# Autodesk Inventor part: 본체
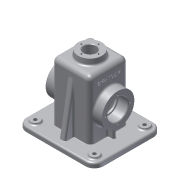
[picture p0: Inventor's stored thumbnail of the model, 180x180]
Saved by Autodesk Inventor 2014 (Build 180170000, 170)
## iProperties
Created: 2016-06
Part Number: 본체
Material: 알루미늄 6061
Document SubType Name: Modeling
Designer: user
Mass: 806.272 g
Surface Area: 909.625 cm^2
Volume: 297.517 cm^3
Density: 2.71 g/cm^3
Appearance: 알루미늄 - 평지
Author: user
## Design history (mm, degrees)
sketch "스케치1"
  geometry: L1 (-50, -52.5)-(50, -52.5); L2 (60, -42.5)-(60, 42.5); L3 (50, 52.5)-(-50, 52.5); L4 (-60, 42.5)-(-60, -42.5); L5 (-60, -52.5)-(60, 52.5); L6 (60, -52.5)-(-60, 52.5); A1 r 10 centre (-50, 42.5) between (-50, 52.5) and (-60, 42.5); A2 r 10 centre (50, 42.5) between (60, 42.5) and (50, 52.5); A3 r 10 centre (50, -42.5) between (50, -52.5) and (60, -42.5); A4 r 10 centre (-50, -42.5) between (-60, -42.5) and (-50, -52.5); 1 further point
  constraints: 12 end point, 8 point on circle, 8 point on line, 8 tangent, 4 centre point, 3 equal radius, 2 midpoint, 2 parallel, 1 horizontal, 1 perpendicular
  dimensions: "d0" = 120 distance of L6.end L5.end; "d1" = 105 distance of L5.end L6.start; "d2" = 10 radius of A1
extrude "돌출1" new body sketch "스케치1" distance "d3" = 2; taper "d4" = 0 deg
sketch "스케치2"
  geometry: L1 (-60, 42.5)-(-60, -42.5) reference; L2 (50, 52.5)-(-50, 52.5) reference; L3 (-60, 42.5)-(-60, -42.5) reference; L4 (-50, -52.5)-(50, -52.5) reference; L5 (60, -42.5)-(60, 42.5) reference; L6 (-50, 57.5)-(50, 57.5); L7 (65, 42.5)-(65, -42.5); L8 (50, -57.5)-(-50, -57.5); L9 (-65, -42.5)-(-65, 42.5); A1 r 10 centre (-50, 42.5) between (-50, 52.5) and (-60, 42.5) reference; A2 r 10 centre (-50, -42.5) between (-60, -42.5) and (-50, -52.5) reference; A3 r 10 centre (50, -42.5) between (50, -52.5) and (60, -42.5) reference; A4 r 10 centre (50, 42.5) between (60, 42.5) and (50, 52.5) reference; A5 r 15 centre (50, 42.5) between (65, 42.5) and (50, 57.5); A6 r 15 centre (50, -42.5) between (50, -57.5) and (65, -42.5); A7 r 15 centre (-50, -42.5) between (-65, -42.5) and (-50, -57.5); A8 r 15 centre (-50, 42.5) between (-50, 57.5) and (-65, 42.5); 1 further point
  constraints: 8 end point, 8 point on circle, 4 centre point, 7 other
  dimensions: "d5" = 5 distance between parallel lines of L1 L9
extrude "돌출2" join sketch "스케치2" distance "d6" = 8; taper "d7" = 0 deg
sketch "스케치3"
  geometry: C1 r 7.5 at (-50, -42.5); C2 r 7.5 at (-50, 42.5); C3 r 7.5 at (50, 42.5); C4 r 7.5 at (50, -42.5); A1 r 15 centre (-50, 42.5) between (-50, 57.5) and (-65, 42.5) reference; A2 r 15 centre (-50, -42.5) between (-65, -42.5) and (-50, -57.5) reference; A3 r 15 centre (50, -42.5) between (50, -57.5) and (65, -42.5) reference; A4 r 15 centre (50, 42.5) between (65, 42.5) and (50, 57.5) reference; 1 further point
  constraints: 4 centre point, 4 coincident
  dimensions: "d8" = 15 diameter of C1; "d9" = 15 diameter of C2; "d10" = 15 diameter of C3; "d11" = 15 diameter of C4
extrude "돌출3" join sketch "스케치3" distance "d12" = 3; taper "d13" = 0 deg
fillet "모깎기1" dims "d14" = 3
sketch "스케치4"
  geometry: C1 r 7.5 at (0, 0) reference; C2 r 7.5 at (100, 0) reference; C3 r 7.5 at (100, -85) reference; C4 r 7.5 at (0, -85) reference; 5 further points
  constraints: 4 coincident
hole "구멍1" sketch "스케치4" at (0, 0), (100, 0), (100, -85), (0, -85) diameter "d15" = 6; stored, may be unused: countersink angle "d19" = 90 deg, drill point angle "d21" = 118 deg; dims "d16" = 6, "d17" = 4, "d18" = 2, "d20" = 8
sketch "스케치5"
  geometry: L1 (-32.5, -32.5)-(32.5, -32.5); L2 (32.5, -32.5)-(32.5, 32.5); L3 (32.5, 32.5)-(-32.5, 32.5); L4 (-32.5, 32.5)-(-32.5, -32.5); L5 (-32.5, -32.5)-(32.5, 32.5); L6 (32.5, -32.5)-(-32.5, 32.5); 1 further point
  constraints: 12 end point, 2 midpoint, 2 parallel, 1 horizontal, 1 perpendicular
  dimensions: "d22" = 65 distance of L3.end L2.end; "d23" = 65 distance of L2.end L1.end
extrude "돌출4" join sketch "스케치5" distance "d24" = 100; taper "d25" = 0 deg
fillet "모깎기2" dims "d26" = 8
fillet "모깎기3" dims "d27" = 8
node "작업 평면1"
sketch "스케치7"
  geometry: C1 r 20 at (0, 0); 1 further point
  constraints: 1 centre point, 1 coincident
  dimensions: "d29" = 40 diameter of C1
extrude "돌출5" join sketch "스케치7" stored distance "d30" = 100; taper "d31" = 5 deg
fillet "모깎기4" dims "d32" = 3
sketch "스케치8"
  geometry: L1 (-27.5, 27.5)-(27.5, 27.5); L2 (27.5, 27.5)-(27.5, -27.5); L3 (27.5, -27.5)-(-27.5, -27.5); L4 (-27.5, -27.5)-(-27.5, 27.5); L5 (-27.5, 27.5)-(27.5, -27.5); L6 (27.5, 27.5)-(-27.5, -27.5); 1 further point
  constraints: 12 end point, 2 midpoint, 2 parallel, 1 horizontal, 1 perpendicular
  dimensions: "d33" = 55 distance of L2.end L3.end; "d34" = 55 distance of L1.end L2.end
extrude "돌출6" cut sketch "스케치8" distance "d35" = 105; taper "d36" = 0 deg
fillet "모깎기5" dims "d37" = 3
fillet "모깎기6" dims "d38" = 3
sketch "스케치9"
  geometry: C1 r 20 at (0, 0) reference; 1 further point
  constraints: 1 coincident
hole "구멍2" sketch "스케치9" at (0, 0) diameter "d39" = 21; stored, may be unused: countersink angle "d43" = 90 deg, drill point angle "d45" = 118 deg; dims "d40" = 6, "d41" = 4, "d42" = 2, "d44" = 8
chamfer "모따기1" distance "d46" = 1; stored, may be unused: second distance "d47" = 2, angle "d48" = 45 deg
sketch "스케치10"
  geometry: C1 r 20 at (0, 0) reference; C2 r 11.5 at (0, 0) reference; A1 r 14.5 centre (0, 0) between (0, 14.5) and (14.5, 0); 2 further points
  constraints: 4 point on circle, 2 horizontal alignment, 2 vertical alignment, 1 centre point, 1 coincident
  dimensions: "d49" = 29 diameter of A1
hole "구멍3" sketch "스케치10" at (0, 14.5), (0, -14.5), (-14.5, 0), (14.5, 0) diameter "d50" = 2.459; stored, may be unused: countersink angle "d54" = 90 deg, drill point angle "d56" = 118 deg; dims "d51" = 7, "d52" = 4, "d53" = 2, "d55" = 9
sketch "스케치11"
  geometry: C1 r 27.5 at (-45, 24.5); 1 further point
  constraints: 1 centre point, 1 horizontal alignment
  dimensions: "d57" = 55 diameter of C1; "d58" = 55 distance of C1.centre point (10, 24.5)
extrude "돌출7" join sketch "스케치11" distance "d59" = 15; taper "d60" = 0 deg
sketch "스케치12"
  geometry: C1 r 27.5 at (0, 0) reference; 2 further points
  constraints: 1 coincident
hole "구멍4" sketch "스케치12" at (0, 0) diameter "d61" = 30; stored, may be unused: countersink angle "d65" = 90 deg, drill point angle "d67" = 0 deg; dims "d62" = 7, "d63" = 35, "d64" = 17, "d66" = 20
chamfer "모따기2" distance "d68" = 1; stored, may be unused: second distance "d69" = 2, angle "d70" = 45 deg
sketch "스케치13"
  geometry: C1 r 27.5 at (0, 0) reference; C2 r 18.5 at (0, 0) reference; A1 r 21 centre (0, 0) between (0, 21) and (21, 0); 3 further points
  constraints: 4 point on circle, 2 horizontal alignment, 2 vertical alignment, 1 centre point, 1 coincident
  dimensions: "d71" = 42 diameter of A1
hole "구멍5" sketch "스케치13" at (0, 21), (0, -21), (-21, 0), (21, 0) diameter "d72" = 3.242; stored, may be unused: countersink angle "d76" = 90 deg, drill point angle "d78" = 118 deg; dims "d73" = 8, "d74" = 35, "d75" = 17, "d77" = 10
sketch "스케치14"
  geometry: L1 (47.5, 27.5)-(32.5, 27.5) reference; L2 (-50, 10)-(50, 10) reference; L3 (42.5, 27.5)-(42.5, 10); L4 (27.5, 0)-(27.5, 102) reference; 1 further point
  constraints: 2 end point, 2 point on line, 1 vertical
  dimensions: "d79" = 15 distance between parallel lines of L3 L4
feature "리브1" sketch "스케치14" dims "d80" = 1, "d81" = 6, "d82" = 0, "d83" = 0, "d84" = 1, "d85" = 1
fillet "모깎기7" dims "d86" = 3
fillet "모깎기8" dims "d87" = 3
sketch "스케치15"
  geometry: L1 (0, -8)-(92, -8) reference; L2 (-18, 4.5)-(-18, 44.5) reference; A1 r 30.5 centre (47, 24.5) between (28.834, 49) and (28.834, 0) reference; 2 further points
  constraints: 1 horizontal alignment, 1 other
  dimensions: "d88" = 32.5 distance from line of point (8, 24.5) L1 (derived); "d89" = 26 distance from line of point (8, 24.5) L2
feature "엠보싱1" sketch "스케치15" dims "d90" = 0.5, "d91" = 0
sketch "스케치16"
  geometry: L1 (-32.5, 10)-(-32.5, 102) reference; L2 (-32, 10)-(-53, 10) reference; L3 (-57.5, 2)-(-57.5, 7) reference; L4 (-47.5, 10)-(-32.5, 95.069); 1 further point
  constraints: 2 end point, 2 point on line
  dimensions: "d92" = 10 deg angle of L4 L3; "d93" = 10 horizontal distance of L3.end L4.start
feature "리브2" sketch "스케치16" dims "d94" = 1, "d95" = 10, "d96" = 0, "d97" = 0, "d98" = 1, "d99" = 1
fillet "모깎기9" dims "d100" = 3
fillet "모깎기10" dims "d101" = 3
fillet "모깎기11" dims "d102" = 1
fillet "모깎기12" dims "d103" = 0.5
node "솔리드1"
mirror "대칭1"
mirror "대칭2"
mirror "대칭3"
node "투영된 루프1"
node "투영된 루프2"
node "투영된 루프3"
node "투영된 루프4"
